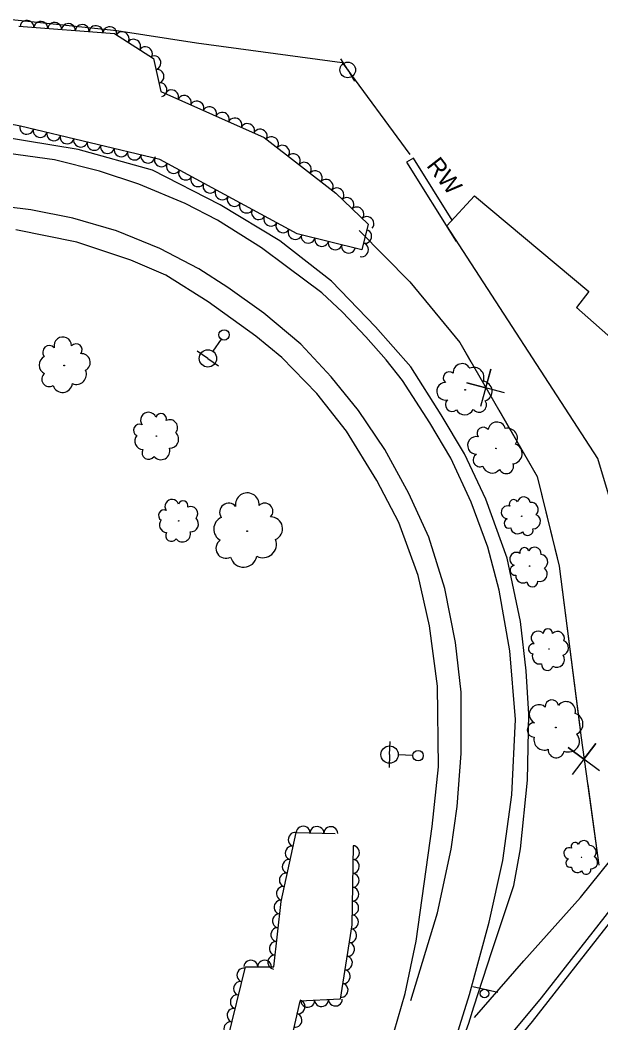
# Model space of a CAD drawing. Extents: x 1722896 to 1754269, y 648279 to 666297.
# Drawn here: x 1726158.6 to 1726326.5, y 657990.5 to 658280.2 of the extents above; entities that cross this region are included whole.
import ezdxf

# ---------------------------------------------------------------- set-up
doc = ezdxf.new("R2010")
doc.units = 0
for name, color, linetype in [('DESIGN - CENTERLINE - Proposed Text', 7, 'Continuous'), ('DESIGN - PUBLIC HEARING - Shapes', 7, 'Continuous'), ('SURVEY - CENTERLINE - Preliminary Text', 7, 'Continuous'), ('SURVEY - CONTROL with Text', 7, 'Continuous'), ('SURVEY - DTM - Breaklines', 7, 'Continuous'), ('SURVEY - VEGETATION - Features with Text', 7, 'Continuous')]:
    doc.layers.add(name, color=color, linetype=linetype)

msp = doc.modelspace()

# ---------------------------------------------------------------- linework, layer by layer
at = {"layer": 'DESIGN - CENTERLINE - Proposed Text'}
for points in [[(1726283.46, 658222.37), (1726272.32, 658240.25), (1726270.28, 658239.08)], [(1726270.28, 658239.08), (1726284.63, 658216.21), (1726284.63, 658216.21), (1726284.8, 658216.37)], [(1726289.95, 658229.36), (1726322.98, 658201.72), (1726319.48, 658197.18), (1726391.81, 658133.27), (1726376.53, 658113.88), (1726355.15, 658131.49), (1726338.04, 658111.98), (1726325.63, 658153.49), (1726281.96, 658220.75), (1726289.95, 658229.36)], [(1726256.57, 658219.36), (1726271.24, 658204.54), (1726285.7, 658187.05), (1726308.1, 658148.33), (1726314.4, 658122.37), (1726320.82, 658072.82), (1726325.93, 658036.04)], [(1726256.57, 658219.36), (1726271.24, 658204.54), (1726285.7, 658187.05), (1726288.93, 658181.47)], [(1726298.61, 658172.52), (1726287.73, 658175.35), (1726293.2, 658173.89), (1726294.66, 658179.35), (1726291.69, 658168.51)], [(1726296.99, 658167.53), (1726308.1, 658148.33), (1726313.81, 658124.8)], [(1726313.81, 658124.8), (1726314.4, 658122.37), (1726320.51, 658075.26)], [(1726326.08, 658063.32), (1726317.07, 658070.04), (1726321.58, 658066.63), (1726324.99, 658071.14), (1726318.16, 658062.21)], [(1726322.7, 658059.31), (1726325.93, 658036.04)]]:
    msp.add_lwpolyline(points, dxfattribs=at)
at = {"layer": 'DESIGN - PUBLIC HEARING - Shapes'}
msp.add_line((1726289.43, 658001.03), (1726296.73, 657999.31), dxfattribs=at)
msp.add_circle((1726292.82, 657998.97), 1.25, dxfattribs=at)
at = {"layer": 'SURVEY - CENTERLINE - Preliminary Text'}
for points in [[(1726016.79, 658285.92), (1726024.89, 658291.66), (1726044.46, 658292.38), (1726072.41, 658289.58), (1726104.41, 658284.74), (1726135.49, 658282.36), (1726158.01, 658280.12), (1726186.55, 658277.18), (1726209.55, 658273.6)], [(1726550.95, 658289.27), (1726522.76, 658255.97), (1726492.93, 658219.65), (1726463.11, 658184.68), (1726432.73, 658149.5), (1726410.6, 658123.35), (1726382.75, 658090.39), (1726376.08, 658082.77), (1726346.72, 658045.84), (1726329.36, 658023.43), (1726309.21, 657997.69), (1726296.29, 657982.25), (1726290.82, 657974.52), (1726288.22, 657972.34), (1726286.31, 657972.14), (1726284.01, 657973.36), (1726283.42, 657976.02), (1726284.67, 657980.29), (1726288.29, 657990.35), (1726289.77, 657995.1)], [(1726209.55, 658273.6), (1726251.71, 658267.9), (1726271.29, 658241.34)], [(1726289.77, 657995.1), (1726294.99, 658011.06), (1726301.29, 658030.12), (1726303.28, 658040.73), (1726305.25, 658060.59), (1726305.66, 658079.61), (1726304.92, 658092.18), (1726303.23, 658106.46), (1726299.37, 658124.7), (1726293.24, 658141.77), (1726287.07, 658154.91), (1726280.32, 658166.1), (1726271.54, 658180.01), (1726261.37, 658191.58), (1726248.63, 658204.73), (1726233.71, 658216.38), (1726216.43, 658226.77), (1726196.91, 658236.81), (1726175.37, 658242.74), (1726152.42, 658246.58)], [(1726282.93, 657980.8), (1726288.5, 657998.69), (1726294.17, 658019.61), (1726298.17, 658037.39), (1726300.74, 658056.37), (1726301.78, 658078.08), (1726300.17, 658097.96), (1726297.13, 658115.44), (1726293.85, 658127.88), (1726288.99, 658140.94), (1726283.13, 658153.6), (1726277.01, 658163.8), (1726269.11, 658176.05), (1726264.43, 658182.03), (1726258.54, 658188.67), (1726251.77, 658195.81), (1726245.86, 658201.35), (1726235.63, 658209.03), (1726228.41, 658214.4), (1726215.66, 658222.33), (1726206.31, 658227.18), (1726192.92, 658232.72), (1726181.57, 658236.55), (1726168.54, 658239.8), (1726152.36, 658242.02)], [(1726271.59, 657996.97), (1726279.28, 658022.24), (1726283.17, 658040.66), (1726284.95, 658052.98), (1726286.12, 658068.28), (1726286.08, 658086.01), (1726284.43, 658100.36), (1726281.33, 658115.98), (1726276.73, 658130.83), (1726271.01, 658143.41), (1726264.03, 658156.14), (1726256.41, 658167.35), (1726248.56, 658177.15), (1726239.71, 658186.56), (1726229.08, 658195.48), (1726218.68, 658202.88), (1726210.23, 658208.28), (1726198.94, 658214.21), (1726186.47, 658219.26), (1726173.82, 658222.92), (1726161.74, 658225.39), (1726146.77, 658227.19)], [(1726269.94, 657998.98), (1726273.07, 658014.06), (1726277.67, 658047.16), (1726279.53, 658064.48), (1726279.21, 658087.79), (1726276.94, 658105.16), (1726273.63, 658119.74), (1726268.1, 658135.07), (1726261.71, 658147.17), (1726252.92, 658161.38), (1726244.4, 658172.29), (1726234.24, 658182.69), (1726226.74, 658188.9), (1726212.96, 658198.82), (1726200.71, 658206.46), (1726190.58, 658210.8), (1726175.01, 658216), (1726157.4, 658219.61)], [(1726289.98, 657992.03), (1726304.17, 658008.43), (1726320.62, 658026.72), (1726329.41, 658037.62), (1726339.51, 658052.8), (1726350.08, 658074), (1726351.31, 658078.56)], [(1726334.46, 658026.39), (1726306.62, 657990.86), (1726285.52, 657965.23)], [(1726194.43, 657873.12), (1726211.7, 657894.12), (1726230.01, 657917.59), (1726239.91, 657932.59), (1726250.95, 657951.58), (1726260.41, 657970.94), (1726266.7, 657987.98), (1726269.94, 657998.98)]]:
    msp.add_lwpolyline(points, dxfattribs=at)
at = {"layer": 'SURVEY - DTM - Breaklines'}
for p, q in [((1726253.3, 658265.76), (1726251.34, 658268.96)), ((1726253.3, 658265.76), (1726255.26, 658262.56)), ((1726216.72, 658187.99), (1726214.3, 658184.49)), ((1726212.88, 658182.43), (1726209.8, 658184.56)), ((1726212.88, 658182.43), (1726215.97, 658180.3)), ((1726265.4, 658067.98), (1726265.54, 658071.73)), ((1726265.4, 658067.98), (1726265.25, 658064.23)), ((1726272.14, 658067.72), (1726267.89, 658067.88))]:
    msp.add_line(p, q, dxfattribs=at)
for centre, radius in [((1726253.3, 658265.76), 2.25), ((1726217.57, 658189.22), 1.5), ((1726212.88, 658182.43), 2.5), ((1726265.4, 658067.98), 2.5), ((1726273.64, 658067.67), 1.5)]:
    msp.add_circle(centre, radius, dxfattribs=at)
at = {"layer": 'SURVEY - VEGETATION - Features with Text'}
for points in [[(1726158.19, 658278.38), (1726185.89, 658276.26), (1726197.13, 658269.1), (1726199.28, 658259.5), (1726229.17, 658246.24), (1726249.83, 658230.12), (1726259.19, 658221.21), (1726257.4, 658213.78), (1726238.71, 658218.38), (1726198.96, 658239.91), (1726158.69, 658249.51), (1726127.96, 658255.47)], [(1726254.83, 658041.66), (1726254.51, 658018.84), (1726251.1, 657997.3), (1726239.45, 657996.78), (1726236.93, 657985.79), (1726240.83, 657969.45), (1726234.67, 657955.87), (1726228.1, 657938.7), (1726212.97, 657912.27), (1726204.26, 657903.09), (1726196.11, 657909.85), (1726192.83, 657932.2), (1726213.03, 657958.74), (1726218.66, 657985.85), (1726223.73, 658006.71), (1726231.94, 658006.68), (1726234.08, 658025.52), (1726238.41, 658045.44), (1726249.65, 658045.23)]]:
    msp.add_lwpolyline(points, dxfattribs=at)
for centre, radius in [((1726171.32, 658180.39), 0.0888), ((1726287.25, 658173.36), 0.089), ((1726197.99, 658159.98), 0.0798), ((1726296.16, 658156.42), 0.0891), ((1726204.44, 658135.5), 0.071), ((1726303.59, 658136.85), 0.0654), ((1726224.26, 658132.51), 0.119), ((1726305.86, 658122.42), 0.067), ((1726311.48, 658098.51), 0.0691), ((1726313.48, 658075.8), 0.0968), ((1726320.89, 658038.32), 0.0571)]:
    msp.add_circle(centre, radius, dxfattribs=at)
for centre, radius, start, end in [((1726170.95, 658186.09), 2.54, 359.816, 193.2357), ((1726167.05, 658184.2), 1.93, 42.4347, 219.7538), ((1726174.8, 658184.92), 1.75, 319.7953, 138.5409), ((1726166.84, 658180.54), 2.74, 117.7217, 244.5674), ((1726176.33, 658181.26), 2.55, 297.6791, 94.4681), ((1726174.87, 658177.81), 2.9, 246.7319, 24.2561), ((1726282.68, 658176.8), 1.75, 50.2164, 228.9621), ((1726286.34, 658178.37), 2.55, 28.1003, 184.8892), ((1726289.8, 658176.93), 2.9, 337.153, 114.6772), ((1726166.97, 658176.39), 2.12, 127.8806, 302.8809), ((1726281.55, 658172.94), 2.54, 90.2371, 283.6568), ((1726292.17, 658172.94), 2.89, 288.0488, 83.8873), ((1726170.87, 658175.48), 2.88, 197.6277, 353.4662), ((1726283.46, 658169.05), 1.94, 132.8558, 310.1749), ((1726291.29, 658169.02), 2.13, 218.3017, 33.302), ((1726195.72, 658164.58), 2.28, 22.2771, 215.6968), ((1726287.13, 658168.86), 2.74, 208.1428, 334.9885), ((1726199.32, 658164.93), 1.57, 342.2564, 161.002), ((1726201.85, 658162.42), 2.29, 320.1402, 116.9292), ((1726296.4, 658161.51), 2.55, 15.1462, 171.9351), ((1726193.13, 658161.68), 1.74, 64.8958, 242.2149), ((1726201.82, 658159.06), 2.6, 269.193, 46.7172), ((1726292.47, 658160.81), 1.75, 37.2623, 216.008), ((1726299.45, 658159.34), 2.91, 324.1989, 101.7232), ((1726194.21, 658158.57), 2.46, 140.1828, 267.0285), ((1726290.5, 658157.29), 2.55, 77.283, 270.7027), ((1726195.74, 658155.17), 1.91, 150.3417, 325.342), ((1726199.29, 658155.75), 2.59, 220.0888, 15.9273), ((1726300.86, 658154.9), 2.89, 275.0947, 70.9332), ((1726291.49, 658153.07), 1.94, 119.9017, 297.2208), ((1726299.12, 658151.29), 2.13, 205.3476, 20.3479), ((1726295.03, 658152.06), 2.75, 195.1887, 322.0344), ((1726224.27, 658140.18), 3.41, 356.0027, 189.4224), ((1726202.51, 658139.64), 2.03, 21.1261, 214.5458), ((1726205.72, 658139.89), 1.4, 341.1054, 159.851), ((1726218.87, 658138), 2.6, 38.6214, 215.9406), ((1726229.32, 658138.28), 2.35, 315.9821, 134.7277), ((1726301.28, 658140.36), 1.29, 30.6897, 209.4354), ((1726304.2, 658140.55), 1.87, 8.5736, 165.3625), ((1726306.24, 658138.7), 2.14, 317.6263, 95.1506), ((1726200.15, 658137.1), 1.55, 63.7447, 241.0639), ((1726207.92, 658137.61), 2.03, 318.9892, 115.7782), ((1726299.54, 658137.97), 1.87, 70.7104, 264.1301), ((1726201.06, 658134.32), 2.19, 139.0318, 265.8775), ((1726207.84, 658134.62), 2.32, 268.042, 45.5662), ((1726218.26, 658133.11), 3.68, 113.9085, 240.7541), ((1726231.05, 658133.23), 3.42, 293.8659, 90.6548), ((1726299.91, 658134.8), 1.42, 113.3291, 290.6482), ((1726306.9, 658135.35), 2.12, 268.5222, 64.3606), ((1726202.36, 658131.26), 1.7, 149.1907, 324.191), ((1726205.53, 658131.72), 2.3, 218.9378, 14.7763), ((1726302.41, 658133.77), 2.02, 188.6162, 315.4618), ((1726305.33, 658132.86), 1.57, 198.7751, 13.7753), ((1726218.06, 658127.54), 2.85, 124.0674, 299.0676), ((1726228.79, 658128.74), 3.9, 242.9186, 20.4429), ((1726302.07, 658124.48), 1.92, 57.5057, 250.9254), ((1726304.37, 658126.46), 1.32, 17.4851, 196.2307), ((1726307.32, 658125.96), 1.92, 355.3689, 152.1578), ((1726223.21, 658125.97), 3.87, 193.8145, 349.653), ((1726308.93, 658123.65), 2.19, 304.4216, 81.9459), ((1726301.7, 658121.23), 1.46, 100.1244, 277.4436), ((1726308.81, 658120.15), 2.17, 255.3175, 51.156), ((1726303.95, 658119.62), 2.07, 175.4115, 302.2571), ((1726306.65, 658118.03), 1.6, 185.5704, 0.5707), ((1726308.33, 658101.64), 1.98, 41.2153, 234.635), ((1726311.17, 658102.95), 1.36, 1.1946, 179.9403), ((1726313.96, 658101.59), 1.98, 339.0785, 135.8674), ((1726307.02, 658098.53), 1.5, 83.834, 261.1531), ((1726314.88, 658098.83), 2.26, 288.1312, 65.6554), ((1726308.78, 658096.29), 2.13, 159.121, 285.9667), ((1726310.99, 658093.93), 1.65, 169.2799, 344.2802), ((1726313.74, 658095.41), 2.24, 239.027, 34.8655), ((1726312.31, 658081.91), 1.9, 8.125, 186.8706), ((1726316.4, 658080.51), 2.77, 346.0088, 142.7977), ((1726308.57, 658079.63), 2.77, 48.1457, 241.5654), ((1726318.15, 658076.83), 3.16, 295.0616, 72.5858), ((1726307.28, 658075.08), 2.11, 90.7643, 268.0835), ((1726317.15, 658071.87), 3.14, 245.9574, 41.7959), ((1726310.11, 658072.26), 2.98, 166.0514, 292.8971), ((1726313.58, 658069.36), 2.32, 176.2103, 351.2106), ((1726319.01, 658041.48), 1.12, 27.9844, 206.7301), ((1726321.56, 658041.52), 1.64, 5.8683, 162.6572), ((1726317.39, 658039.46), 1.63, 68.0051, 261.4248), ((1726323.27, 658039.83), 1.87, 314.921, 92.4452), ((1726317.59, 658036.68), 1.24, 110.6238, 287.9429), ((1726323.71, 658036.87), 1.85, 265.8168, 61.6553), ((1726319.72, 658035.68), 1.76, 185.9108, 312.7565), ((1726322.23, 658034.76), 1.37, 196.0697, 11.07)]:
    msp.add_arc(centre, radius, start, end, dxfattribs=at)
for centre, major_axis in [((1726160.59, 658278.19), (1.99, -0.15)), ((1726164.58, 658277.89), (1.99, -0.15)), ((1726168.57, 658277.58), (1.99, -0.15)), ((1726172.56, 658277.28), (1.99, -0.15)), ((1726176.55, 658276.98), (1.99, -0.15)), ((1726180.54, 658276.67), (1.99, -0.15)), ((1726184.52, 658276.37), (1.99, -0.15)), ((1726188.11, 658274.85), (1.69, -1.07)), ((1726191.48, 658272.7), (1.69, -1.07)), ((1726194.86, 658270.55), (1.69, -1.07)), ((1726197.42, 658267.83), (0.44, -1.95)), ((1726198.29, 658263.93), (0.44, -1.95)), ((1726199.16, 658260.03), (0.44, -1.95)), ((1726202.44, 658258.09), (1.83, -0.81)), ((1726206.1, 658256.47), (1.83, -0.81)), ((1726209.75, 658254.85), (1.83, -0.81)), ((1726213.41, 658253.23), (1.83, -0.81)), ((1726217.07, 658251.61), (1.83, -0.81)), ((1726220.72, 658249.98), (1.83, -0.81)), ((1726224.38, 658248.36), (1.83, -0.81)), ((1726160.5, 658249.08), (-1.95, 0.46)), ((1726164.39, 658248.15), (-1.95, 0.46)), ((1726168.28, 658247.22), (-1.95, 0.46)), ((1726228.04, 658246.74), (1.83, -0.81)), ((1726172.17, 658246.3), (-1.95, 0.46)), ((1726176.07, 658245.37), (-1.95, 0.46)), ((1726179.96, 658244.44), (-1.95, 0.46)), ((1726231.35, 658244.54), (1.58, -1.23)), ((1726183.85, 658243.51), (-1.95, 0.46)), ((1726187.74, 658242.59), (-1.95, 0.46)), ((1726191.63, 658241.66), (-1.95, 0.46)), ((1726234.5, 658242.08), (1.58, -1.23)), ((1726195.52, 658240.73), (-1.95, 0.46)), ((1726199.37, 658239.69), (-1.76, 0.95)), ((1726237.65, 658239.62), (1.58, -1.23)), ((1726240.81, 658237.16), (1.58, -1.23)), ((1726202.89, 658237.78), (-1.76, 0.95)), ((1726206.4, 658235.88), (-1.76, 0.95)), ((1726243.96, 658234.7), (1.58, -1.23)), ((1726209.92, 658233.97), (-1.76, 0.95)), ((1726247.12, 658232.24), (1.58, -1.23)), ((1726213.44, 658232.07), (-1.76, 0.95)), ((1726216.95, 658230.16), (-1.76, 0.95)), ((1726250.24, 658229.74), (1.45, -1.38)), ((1726220.47, 658228.26), (-1.76, 0.95)), ((1726253.13, 658226.98), (1.45, -1.38)), ((1726223.99, 658226.35), (-1.76, 0.95)), ((1726227.5, 658224.45), (-1.76, 0.95)), ((1726256.03, 658224.22), (1.45, -1.38)), ((1726231.02, 658222.54), (-1.76, 0.95)), ((1726234.54, 658220.64), (-1.76, 0.95)), ((1726258.92, 658221.46), (1.45, -1.38)), ((1726238.06, 658218.73), (-1.76, 0.95)), ((1726258.33, 658217.67), (-0.47, -1.94)), ((1726241.87, 658217.6), (-1.94, 0.48)), ((1726245.76, 658216.64), (-1.94, 0.48)), ((1726249.64, 658215.69), (-1.94, 0.48)), ((1726253.52, 658214.73), (-1.94, 0.48)), ((1726257.4, 658213.79), (-0.47, -1.94)), ((1726237.99, 658043.48), (0.43, 1.95)), ((1726240.41, 658045.41), (2, -0.04)), ((1726244.41, 658045.33), (2, -0.04)), ((1726248.41, 658045.26), (2, -0.04)), ((1726237.14, 658039.58), (0.43, 1.95)), ((1726254.8, 658039.66), (-0.03, -2)), ((1726236.28, 658035.67), (0.43, 1.95)), ((1726254.75, 658035.66), (-0.03, -2)), ((1726235.43, 658031.76), (0.43, 1.95)), ((1726254.69, 658031.66), (-0.03, -2)), ((1726234.58, 658027.85), (0.43, 1.95)), ((1726254.63, 658027.66), (-0.03, -2)), ((1726233.9, 658023.92), (0.23, 1.99)), ((1726254.58, 658023.66), (-0.03, -2)), ((1726233.44, 658019.94), (0.23, 1.99)), ((1726254.52, 658019.66), (-0.03, -2)), ((1726232.99, 658015.97), (0.23, 1.99)), ((1726254.01, 658015.7), (-0.31, -1.98)), ((1726232.54, 658011.99), (0.23, 1.99)), ((1726253.39, 658011.75), (-0.31, -1.98)), ((1726232.09, 658008.02), (0.23, 1.99)), ((1726225.28, 658006.71), (2, -0.01)), ((1726229.28, 658006.69), (2, -0.01)), ((1726252.76, 658007.8), (-0.31, -1.98)), ((1726223.15, 658004.33), (0.47, 1.94)), ((1726252.14, 658003.85), (-0.31, -1.98)), ((1726222.21, 658000.44), (0.47, 1.94)), ((1726251.51, 657999.9), (-0.31, -1.98)), ((1726221.26, 657996.56), (0.47, 1.94)), ((1726239.07, 657995.12), (-0.45, -1.95)), ((1726241.74, 657996.88), (-2, -0.09)), ((1726245.73, 657997.06), (-2, -0.09)), ((1726249.73, 657997.24), (-2, -0.09)), ((1726220.32, 657992.67), (0.47, 1.94)), ((1726238.17, 657991.22), (-0.45, -1.95)), ((1726219.37, 657988.78), (0.47, 1.94))]:
    msp.add_ellipse(centre, major_axis=major_axis, ratio=0.940188, start_param=0, end_param=3.141593, dxfattribs=at)

# ---------------------------------------------------------------- texts
at = {"layer": 'SURVEY - CONTROL with Text'}
msp.add_text('RW', height=5, rotation=307.935, dxfattribs=at).set_placement((1726275.89, 658238.06))

doc.saveas('drawing.dxf')
